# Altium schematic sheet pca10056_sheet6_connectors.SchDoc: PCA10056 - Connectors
size A3; Organization: Nordic Semiconductor; DocumentNumber: 6; SheetNumber: 6; SheetTotal: 7; CompanyName: Nordic Semiconductor
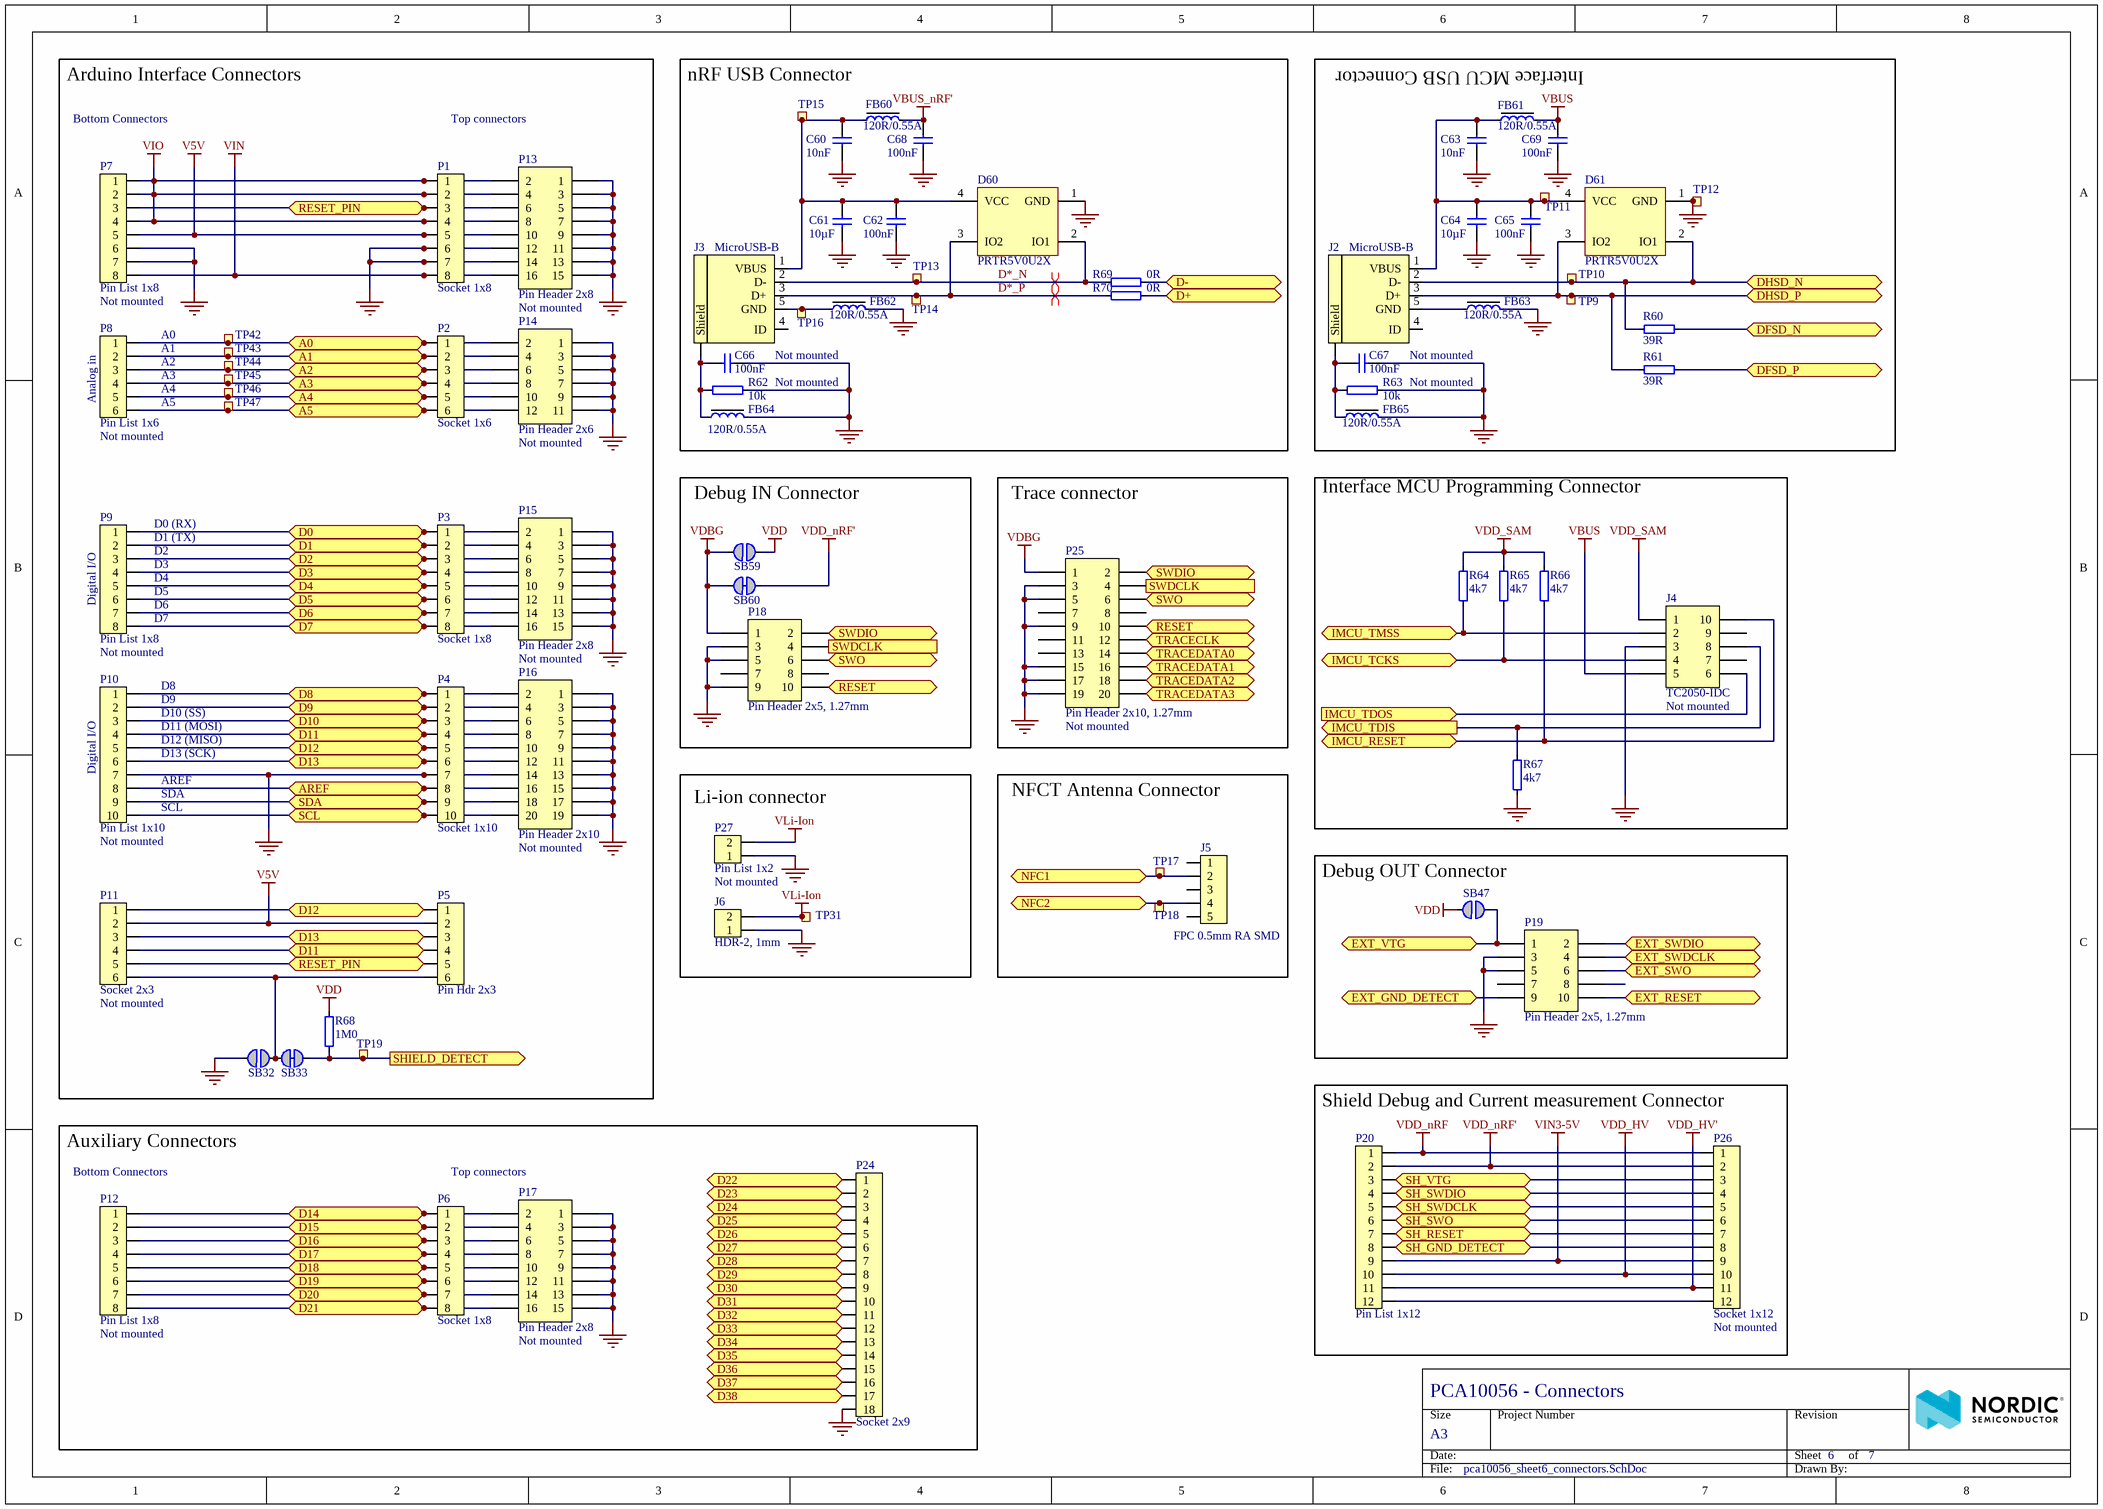
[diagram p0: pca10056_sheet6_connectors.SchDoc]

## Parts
C60  10nF  [CAPC1005X04L]
C61  10µF  [CAPC1608X06L]
C62  100nF  [CAPC1005X04L]
C63  10nF  [CAPC1005X04L]
C64  10µF  [CAPC1608X06L]
C65  100nF  [CAPC1005X04L]
C66  100nF  Assembly: Not mounted  [CAPC1005X04L]
C67  100nF  Assembly: Not mounted  [CAPC1005X04L]
C68  100nF  [CAPC1005X04L]
C69  100nF  [CAPC1005X04L]
D60  PRTR5V0U2X  [SOT190P230X110-4L]
D61  PRTR5V0U2X  [SOT190P230X110-4L]
FB60  120R/0.55A  [INDC1005X04L]
FB61  120R/0.55A  [INDC1005X04L]
FB62  120R/0.55A  [INDC1005X04L]
FB63  120R/0.55A  [INDC1005X04L]
FB64  120R/0.55A  [INDC1005X04L]
FB65  120R/0.55A  [INDC1005X04L]
J2  MicroUSB-B  [USB-Micro-B-RA-SMD-PiP]
J3  MicroUSB-B  [USB-Micro-B-RA-SMD-PiP]
J4  TC2050-IDC  Assembly: Not mounted  [TC2050-IDC-NLFP]
J5  FPC 0.5mm RA SMD  [FPC_05P-0.5mm-RA-SMD]
J6  HDR-2, 1mm  [SM02B-SRSS-TB]
P1  Socket 1x8  [SOCKET_1x8_SMD]
P2  Socket 1x6  [SOCKET_1x6_SMD]
P3  Socket 1x8  [SOCKET_1x8_SMD]
P4  Socket 1x10  [SOCKET_1x10_SMD]
P5  Pin Hdr 2x3  [HDR_2x3-SMD]
P6  Socket 1x8  [SOCKET_1x8_SMD]
P7  Pin List 1x8  Assembly: Not mounted  [LIST_1x8_SMD-NC]
P8  Pin List 1x6  Assembly: Not mounted  [LIST_1x6_SMD-NC]
P9  Pin List 1x8  Assembly: Not mounted  [LIST_1x8_SMD-NC]
P10  Pin List 1x10  Assembly: Not mounted  [LIST_1x10_SMD-NC]
P11  Socket 2x3  Assembly: Not mounted  [SOCKET_2x3_SMD-2.54mm-bottom-NC]
P12  Pin List 1x8  Assembly: Not mounted  [LIST_1x8_SMD-NC]
P13  Pin Header 2x8  Assembly: Not mounted  [HDR_2x8-NC]
P14  Pin Header 2x6  Assembly: Not mounted  [HDR_2x6-NC]
P15  Pin Header 2x8  Assembly: Not mounted  [HDR_2x8-NC]
P16  Pin Header 2x10  Assembly: Not mounted  [HDR_2x10-NC]
P17  Pin Header 2x8  Assembly: Not mounted  [HDR_2x8-NC]
P18  Pin Header 2x5, 1.27mm  [HDR_2x5-SMD-1.27mm-K]
P19  Pin Header 2x5, 1.27mm  [HDR_2x5-SMD-1.27mm-K]
P20  Pin List 1x12  [LIST_1x12_SMD]
P24  Socket 2x9  [SOCKET_2x9_SMD-2.54mm]
P25  Pin Header 2x10, 1.27mm  Assembly: Not mounted  [HDR_2x10-SMD-1.27mm-NC]
P26  Socket 1x12  Assembly: Not mounted  [LIST_1x12_SMD-NC]
P27  Pin List 1x2  Assembly: Not mounted  [LIST_1x2-NC]
R60  39R  [RESC1005X04L]
R61  39R  [RESC1005X04L]
R62  10k  Assembly: Not mounted  [RESC1005X04L]
R63  10k  Assembly: Not mounted  [RESC1005X04L]
R64  4k7  [RESC1005X04L]
R65  4k7  [RESC1005X04L]
R66  4k7  [RESC1005X04L]
R67  4k7  [RESC1005X04L]
R68  1M0  [RESC1005X04L]
R69  0R  [RESC1005X04L]
R70  0R  [RESC1005X04L]
SB32  Solderbridge  [Solderbridge]  (value not drawn)  (no BOM)
SB33  Solderbridge  [Solderbridge_Shorted]  (value not drawn)  (net tie, no BOM)
SB47  Solderbridge  [Solderbridge]  (value not drawn)  (no BOM)
SB59  Solderbridge  [Solderbridge]  (value not drawn)  (no BOM)
SB60  Solderbridge  [Solderbridge_Shorted]  (value not drawn)  (net tie, no BOM)
TP9  Ø1.0mm,SMD  [TP_SMD_Ø1.0mm]  (value not drawn)  (no BOM)
TP10  Ø1.0mm,SMD  [TP_SMD_Ø1.0mm]  (value not drawn)  (no BOM)
TP11  Ø1.0mm,SMD  [TP_SMD_Ø1.0mm]  (value not drawn)  (no BOM)
TP12  Ø1.0mm,SMD  [TP_SMD_Ø1.0mm]  (value not drawn)  (no BOM)
TP13  Ø1.5mm,SMD  [TP_SMD_Ø1.5mm]  (value not drawn)  (no BOM)
TP14  Ø1.5mm,SMD  [TP_SMD_Ø1.5mm]  (value not drawn)  (no BOM)
TP15  Ø1.5mm,SMD  [TP_SMD_Ø1.5mm]  (value not drawn)  (no BOM)
TP16  Ø1.5mm,SMD  [TP_SMD_Ø1.5mm]  (value not drawn)  (no BOM)
TP17  Ø1.0mm,SMD  [TP_SMD_Ø1.0mm]  (value not drawn)  (no BOM)
TP18  Ø1.0mm,SMD  [TP_SMD_Ø1.0mm]  (value not drawn)  (no BOM)
TP19  Ø1.0mm,SMD  [TP_SMD_Ø1.0mm]  (value not drawn)  (no BOM)
TP31  Ø1.0mm,SMD  [TP_SMD_Ø1.0mm]  (value not drawn)  (no BOM)
TP42  Ø1.0mm,SMD  [TP_SMD_Ø1.0mm]  (value not drawn)  (no BOM)
TP43  Ø1.0mm,SMD  [TP_SMD_Ø1.0mm]  (value not drawn)  (no BOM)
TP44  Ø1.0mm,SMD  [TP_SMD_Ø1.0mm]  (value not drawn)  (no BOM)
TP45  Ø1.0mm,SMD  [TP_SMD_Ø1.0mm]  (value not drawn)  (no BOM)
TP46  Ø1.0mm,SMD  [TP_SMD_Ø1.0mm]  (value not drawn)  (no BOM)
TP47  Ø1.0mm,SMD  [TP_SMD_Ø1.0mm]  (value not drawn)  (no BOM)

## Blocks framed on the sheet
Arduino Interface Connectors: P1-P5 P7-P11 P13-P16 R68 SB32 SB33 TP19 TP42-TP47
nRF USB Connector: C60-C62 C66 C68 D60 FB60 FB62 FB64 J3 R62 R69 R70 TP13-TP16
Interface MCU USB Connector: C63-C65 C67 C69 D61 FB61 FB63 FB65 J2 R60 R61 R63 TP9-TP12
Debug IN Connector: P18 SB59 SB60
Trace connector: P25
Interface MCU Programming Connector: J4 R64-R67
Li-ion connector: J6 P27 TP31
NFCT Antenna Connector: J5 TP17 TP18
Debug OUT Connector: P19 SB47
Shield Debug and Current measurement Connector: P20 P26
Auxiliary Connectors: P6 P12 P17 P24

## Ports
A0 (bidir), A1 (bidir), A2 (bidir), A3 (bidir), A4 (bidir), A5 (bidir), AREF (bidir), D0 (bidir), D1 (bidir), D2 (bidir), D3 (bidir), D4 (bidir), D5 (bidir), D6 (bidir), D7 (bidir), D8 (bidir), D9 (bidir), D10 (bidir), D11 (bidir), D12 (bidir), D13 (bidir), D14 (bidir), D15 (bidir), D16 (bidir), D17 (bidir), D18 (bidir), D19 (bidir), D20 (bidir), D21 (bidir), D22 (bidir), D23 (bidir), D24 (bidir), D25 (bidir), D26 (bidir), D27 (bidir), D28 (bidir), D29 (bidir), D30 (bidir), D31 (bidir), D32 (bidir), D33 (bidir), D34 (bidir), D35 (bidir), D36 (bidir), D37 (bidir), D38 (bidir), D+ (bidir), D- (bidir), DFSD_N (bidir), DFSD_P (bidir), DHSD_N (bidir), DHSD_P (bidir), EXT_GND_DETECT (bidir), EXT_RESET (bidir), EXT_SWDCLK (bidir), EXT_SWDIO (bidir), EXT_SWO (bidir), EXT_VTG (bidir), IMCU_RESET (bidir), IMCU_TCKS (bidir), IMCU_TDIS (out), IMCU_TDOS (in), IMCU_TMSS (bidir), NFC1 (bidir), NFC2 (bidir), RESET (bidir), RESET_PIN (bidir), SCL (bidir), SDA (bidir), SH_GND_DETECT (bidir), SH_RESET (bidir), SH_SWDCLK (bidir), SH_SWDIO (bidir), SH_SWO (bidir), SH_VTG (bidir), SHIELD_DETECT (out), SWDCLK (out), SWDIO (bidir), SWO (bidir), TRACECLK (bidir), TRACEDATA0 (bidir), TRACEDATA1 (bidir), TRACEDATA2 (bidir), TRACEDATA3 (bidir)

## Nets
GND: C60.1 C61.1 C62.1 C63.2 C64.1 C65.1 C66.1 C67.1 C68.1 C69.1 D60.1(GND) D61.1(GND) FB62.2 FB63.2 FB64.2 FB65.2 J4.3 J6.1 P1.6 P1.7 P4.7 P7.6 P7.7 P10.7 P13.1 P13.3 P13.5 P13.7 P13.9 P13.11 P13.12 P13.13 P13.14 P13.15 P14.1 P14.3 P14.5 P14.7 P14.9 P14.11 P15.1 P15.3 P15.5 P15.7 P15.9 P15.11 P15.13 P15.15 P16.1 P16.3 P16.5 P16.7 P16.9 P16.11 P16.13 P16.14 P16.15 P16.17 P16.19 P17.1 P17.3 P17.5 P17.7 P17.9 P17.11 P17.13 P17.15 P18.3 P18.5 P18.9 P19.3 P19.5 P24.18 P25.3 P25.5 P25.9 P25.15 P25.17 P25.19 P27.1 R62.1 R63.1 R67.2 SB32.1 TP12.1
V5V: P1.5 P5.2 P7.5 P11.2 P13.10
VBUS: C69.2 FB61.2 J4.5
VBUS_nRF': C68.2 FB60.2
VDBG: P18.1 P25.1 SB59.1 SB60.1
VDD: R68.2 SB47.1 SB59.2
VDD_HV: P20.10 P26.10
VDD_HV': P20.11 P26.11
VDD_nRF: P20.1 P26.1
VDD_nRF': P20.2 P26.2 SB60.2
VDD_SAM: J4.1 R64.2 R65.2 R66.2
VIN: P1.8 P7.8 P13.16
VIN3-5V: P20.9 P26.9
VIO: P1.1 P1.2 P1.4 P7.1 P7.2 P7.4 P13.2 P13.4 P13.8
VLi-Ion: J6.2 P27.2 TP31.1
A0: P2.1 P8.1 P14.2 TP42.1 ; port A0
A1: P2.2 P8.2 P14.4 TP43.1 ; port A1
A2: P2.3 P8.3 P14.6 TP44.1 ; port A2
A3: P2.4 P8.4 P14.8 TP45.1 ; port A3
A4: P2.5 P8.5 P14.10 TP46.1 ; port A4
A5: P2.6 P8.6 P14.12 TP47.1 ; port A5
AREF: P4.8 P10.8 P16.16 ; port AREF
D0: P3.1 P9.1 P15.2 ; port D0
D1: P3.2 P9.2 P15.4 ; port D1
D2: P3.3 P9.3 P15.6 ; port D2
D3: P3.4 P9.4 P15.8 ; port D3
D4: P3.5 P9.5 P15.10 ; port D4
D5: P3.6 P9.6 P15.12 ; port D5
D6: P3.7 P9.7 P15.14 ; port D6
D7: P3.8 P9.8 P15.16 ; port D7
D8: P4.1 P10.1 P16.2 ; port D8
D9: P4.2 P10.2 P16.4 ; port D9
D10: P4.3 P10.3 P16.6 ; port D10
D11: P4.4 P5.4 P10.4 P11.4 P16.8 ; port D11
D12: P4.5 P5.1 P10.5 P11.1 P16.10 ; port D12
D13: P4.6 P5.3 P10.6 P11.3 P16.12 ; port D13
D14: P6.1 P12.1 P17.2 ; port D14
D15: P6.2 P12.2 P17.4 ; port D15
D16: P6.3 P12.3 P17.6 ; port D16
D17: P6.4 P12.4 P17.8 ; port D17
D18: P6.5 P12.5 P17.10 ; port D18
D19: P6.6 P12.6 P17.12 ; port D19
D20: P6.7 P12.7 P17.14 ; port D20
D21: P6.8 P12.8 P17.16 ; port D21
D22: P24.1 ; port D22
D23: P24.2 ; port D23
D24: P24.3 ; port D24
D25: P24.4 ; port D25
D26: P24.5 ; port D26
D27: P24.6 ; port D27
D28: P24.7 ; port D28
D29: P24.8 ; port D29
D30: P24.9 ; port D30
D31: P24.10 ; port D31
D32: P24.11 ; port D32
D33: P24.12 ; port D33
D34: P24.13 ; port D34
D35: P24.14 ; port D35
D36: P24.15 ; port D36
D37: P24.16 ; port D37
D38: P24.17 ; port D38
D*_N: D60.2(IO1) J3.2(D-) R69.2 TP13.1
D*_P: D60.3(IO2) J3.3(D+) R70.2 TP14.1
D+: R70.1 ; port D+
D-: R69.1 ; port D-
DFSD_N: R60.1 ; port DFSD_N
DFSD_P: R61.1 ; port DFSD_P
DHSD_N: D61.2(IO1) J2.2(D-) R60.2 TP10.1 ; port DHSD_N
DHSD_P: D61.3(IO2) J2.3(D+) R61.2 TP9.1 ; port DHSD_P
EXT_GND_DETECT: P19.9 ; port EXT_GND_DETECT
EXT_RESET: P19.10 ; port EXT_RESET
EXT_SWDCLK: P19.4 ; port EXT_SWDCLK
EXT_SWDIO: P19.2 ; port EXT_SWDIO
EXT_SWO: P19.6 ; port EXT_SWO
EXT_VTG: P19.1 SB47.2 ; port EXT_VTG
IMCU_RESET: J4.10 R66.1 ; port IMCU_RESET
IMCU_TCKS: J4.4 R65.1 ; port IMCU_TCKS
IMCU_TDIS: J4.8 R67.1 ; port IMCU_TDIS
IMCU_TDOS: J4.6 ; port IMCU_TDOS
IMCU_TMSS: J4.2 R64.1 ; port IMCU_TMSS
NFC1: J5.2 TP17.1 ; port NFC1
NFC2: J5.4 TP18.1 ; port NFC2
RESET: P18.10 P25.10 ; port RESET
RESET_PIN: P1.3 P5.5 P7.3 P11.5 P13.6 ; port RESET_PIN
SCL: P4.10 P10.10 P16.20 ; port SCL
SDA: P4.9 P10.9 P16.18 ; port SDA
SH_GND_DETECT: P20.8 P26.8 ; port SH_GND_DETECT
SH_RESET: P20.7 P26.7 ; port SH_RESET
SH_SWDCLK: P20.5 P26.5 ; port SH_SWDCLK
SH_SWDIO: P20.4 P26.4 ; port SH_SWDIO
SH_SWO: P20.6 P26.6 ; port SH_SWO
SH_VTG: P20.3 P26.3 ; port SH_VTG
SHIELD_DETECT: R68.1 SB33.2 TP19.1 ; port SHIELD_DETECT
SWDCLK: P18.4 P25.4 ; port SWDCLK
SWDIO: P18.2 P25.2 ; port SWDIO
SWO: P18.6 P25.6 ; port SWO
TRACECLK: P25.12 ; port TRACECLK
TRACEDATA0: P25.14 ; port TRACEDATA0
TRACEDATA1: P25.16 ; port TRACEDATA1
TRACEDATA2: P25.18 ; port TRACEDATA2
TRACEDATA3: P25.20 ; port TRACEDATA3
NetC60_2: C60.2 C61.2 C62.2 D60.4(VCC) FB60.1 J3.1(VBUS) TP15.1
NetC63_1: C63.1 C64.2 C65.2 D61.4(VCC) FB61.1 J2.1(VBUS) TP11.1
NetC66_2: C66.2 FB64.1 J3.6(Shield) R62.2
NetC67_2: C67.2 FB65.1 J2.6(Shield) R63.2
NetFB62_1: FB62.1 J3.5(GND) TP16.1
NetFB63_1: FB63.1 J2.5(GND)
NetP5_6: P5.6 P11.6 SB32.2 SB33.1
NetP20_12: P20.12 P26.12

Not connected (* = marked no-connect by the designer): J2 4(ID); J3 4(ID); J4 7 9; J5 1 3 5; P18 7 8; P19 7 8; P25 7 8 11 13

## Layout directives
differential pair: D*_N, D*_P

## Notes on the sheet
- Bottom Connectors
- Top connectors
- (near P8) A0
- (near P8) A1
- (near P8) A2
- (near P8) A3
- (near P8) Analog in
- (near P8) A4
- (near P8) A5
- (near P9) D0 (RX)
- (near P9) D1 (TX)
- (near P9) D2
- (near P9) D3
- (near P9) D4
- (near P9) Digital I/O
- (near P9) D5
- (near P9) D6
- (near P9) D7
- (near P10) D8
- (near P10) D9
- (near P10) D10 (SS)
- (near P10) Digital I/O
- (near P10) AREF
- (near P10) D11 (MOSI)
- (near P10) D12 (MISO)
- (near P10) D13 (SCK)
- (near P10) SDA
- (near P10) SCL
- (near P12) Bottom Connectors

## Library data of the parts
C60 C63 = C0402-10n: Capacitor, X7R, ±10%; Part number IPS: 00000007784; Note: 16V; Artikkelnr Noca: 20039166; Artikkelnr Simpro: N.A.
C61 C64 = C0603-10µ: Capacitor, X5R, ±20%; Part number IPS: 00000007785; Note: 6.3V; Artikkelnr Noca: 20039234; Artikkelnr Simpro: N.A.
C62 C65-C69 = C0402-100n: Capacitor, X7R, ±10%; Part number IPS: 00000005296; Note: 16V; Artikkelnr Noca: 20039200; Artikkelnr Simpro: N.A.
D60 D61 = PRTR5V0U2X: Ultra low capacitance double rail-to-rail ESD protection diode; Manufacturer: NXP; 2nd source part number: 152-4157; Artikkelnr Noca: 10069015; Artikkelnr Simpro: N.A.
FB60-FB65 = FB0402-120R@100M-500mA: Ferrite Bead, 120 Ohm @ 100MHz, 500mA, 250 mOhm Max; Manufacturer: Murata; Manufacturer Part Number: BLM15AG121SN1D; 2nd source part number: 151-5760; Note: Chip EMIFIL Inductor Type Chip Ferrite Bead; Artikkelnr Noca: 33029317; Artikkelnr Simpro: N.A.
J2 J3 = USB-Micro-B-RA-SMD-PiP: MicroUSB-B-SMT; Manufacturer: Allen Creations Corp.; Manufacturer Part Number: AJU55-BS2111-L; 2nd source part number: 609-4616-1-ND; Part number IPS: 00000007790; Artikkelnr Noca: 55029020; Artikkelnr Simpro: N.A.
J4 = TC2050-IDC-NLFP: CBL PLUG-OF-NAILS 10-PIN; Manufacturer: Tag-Connect LLC; Artikkelnr Noca: N.A.
J5 = FPC_05P-0.5mm-RA-SMD: 0.5mm FPC, 5P,Right Angle SMT,Double Contact,H=1.2mm,White, Tin plated; Manufacturer: W-CON; Manufacturer Part Number: 5141-05RZDNWR01; 2nd source part number: WM9836CT-ND; Part number IPS: 00000007792; Artikkelnr Noca: 55010020; Artikkelnr Simpro: N.A.
J6 = SM02B-SRSS-TB: 1.0mm pitch connector side entry SMD; Manufacturer: JST; Manufacturer Part Number: SM02B-SRSS-TB(LF)(SN); Part number IPS: 00000007791; Note: JST, Header; Artikkelnr Noca: 55010030; Artikkelnr Simpro: N.A.
P1 P3 P6 = Socket 1x8 SMD: Socket 1x8, 2.54mm (100mil), SMD; Manufacturer: W-CON; Manufacturer Part Number: 2171-108MS0CUNR1; 2nd source part number: SSM-108-F-SV-P-TR; Artikkelnr Noca: 55030002; Artikkelnr Simpro: N.A.
P2 = Socket 1x6 SMD: Socket 1x6, 2.54mm (100mil), SMD; Manufacturer: W-CON; Manufacturer Part Number: 2171-106MS0CUNR1; 2nd source part number: SSM-106-F-SV-P-TR; Artikkelnr Noca: 55030001; Artikkelnr Simpro: N.A.
P4 = Socket 1x10 SMD: Socket 1x10, 2.54mm (100mil), SMD; Manufacturer: W-CON; Manufacturer Part Number: 2171-110MS0CUNR1; 2nd source part number: SSM-110-F-SV-P-TR; Artikkelnr Noca: 55030004; Artikkelnr Simpro: N.A.
P5 = Pin Header 2x3 SMD: Pin Header 2x3, 2.54mm (100mil) SMD; Manufacturer: W-CON; Manufacturer Part Number: 1125-1203S0M116R1; 2nd source part number: TSM-103-01-L-DV; Artikkelnr Noca: 55010007; Artikkelnr Simpro: N.A.
P7 P9 P12 = Pin List 1x8 SMD, N.C.: Pin List 1x8, 2.54mm (100mil), SMD; Manufacturer: W-CON; Manufacturer Part Number: 1125-1108S0M116R2; 2nd source part number: TSM-108-01-L-SV-P-TR; Artikkelnr Noca: 55010006; Artikkelnr Simpro: N.A.
P8 = Pin List 1x6 SMD, N.C.: Pin List 1x6, 2.54mm (100mil), SMD; Manufacturer: W-CON; Manufacturer Part Number: 1125-1106S0M116R2; 2nd source part number: TSM-106-01-L-SV-P-TR; Artikkelnr Noca: 55010026; Artikkelnr Simpro: N.A.
P10 = Pin List 1x10 SMD, N.C.: Pin List 1x10, 2.54mm (100mil), SMD; Manufacturer: W-CON; Manufacturer Part Number: 1125-1110S0M116R2; 2nd source part number: TSM-110-01-L-SV-P-TR; Artikkelnr Noca: 55010028; Artikkelnr Simpro: N.A.
P11 = Socket 2x3 SMD Bottom, N.C.: Socket 2x3, 2.54mm (100mil), SMD; Manufacturer: W-CON; Manufacturer Part Number: 2171-203MS0CUNR1; 2nd source part number: SSM-103-F-DV-P-TR; Artikkelnr Noca: 55030010; Artikkelnr Simpro: N.A.
P13 P15 P17 = Pin Header 2x8, N.C.: Pin Header 2x8, 2.54mm (100mil); Artikkelnr Noca: N.A.
P14 = Pin Header 2x6, N.C.: Pin Header 2x6, 2.54mm (100mil); Artikkelnr Noca: N.A.
P16 = Pin Header 2x10, N.C.: Pin Header 2x10, 2.54mm (100mil); Artikkelnr Noca: N.A.
P18 P19 = Pin Header 2x5 SMD, 1.27mm, KS: Pin Header 2x5, 1.27mm (50mil), SMD, Keying Shroud; Manufacturer: W-CON; Manufacturer Part Number: 3132-10MS0BK00R1; 2nd source part number: FTSH-105-01-F-DV-K; Artikkelnr Noca: 55010009; Artikkelnr Simpro: N.A.
P20 = Pin List 1x12 SMD: Pin List 1x12, 2.54mm (100mil), SMD; Artikkelnr Noca: 55019293; Artikkelnr Simpro: N.A.
P24 = Socket 2x9 SMD: Socket 2x9, 2.54mm (100mil), SMD; Manufacturer: Samtec; Manufacturer Part Number: SSM-109-F-DV; Artikkelnr Noca: 55030011; Artikkelnr Simpro: N.A.
P25 = Pin Header 2x10 SMD, 1.27mm, KS, N.C.: Pin Header 2x10, 1.27mm (50mil), SMD, Keying Shroud; Manufacturer: Samtec; Manufacturer Part Number: FTSH-110-01-F-DV-K; Artikkelnr Noca: N.A.
P26 = Socket 1x12 SMD, N.C.: Socket 1x12, 2.54mm (100mil), SMD; Manufacturer: Samtec; Manufacturer Part Number: SSM-109-L-SV; Artikkelnr Noca: N.A.
P27 = Pin List 1x2, N.C.: Pin List 1x2, 2.54mm (100mil); Artikkelnr Noca: N.A.
R60 R61 = R0402-39R: Resistor, ±1%, 0.063W; Part number IPS: 00000000821; Note: Chip Res 1%; Artikkelnr Noca: 27049039; Artikkelnr Simpro: N.A.; Value Ohm: 39
R62 R63 = R0402-10k: Resistor, ±1%, 0.063W; Part number IPS: 00000002093; Note: Chip Res 1%; Artikkelnr Noca: 27049097; Artikkelnr Simpro: N.A.; Value Ohm: 10000
R64-R67 = R0402-4k7: Resistor, ±1%, 0.063W; Part number IPS: 00000003433; Note: Chip Res 1%; Artikkelnr Noca: 27049089; Artikkelnr Simpro: N.A.; Value Ohm: 4700
R68 = R0402-1M0: Resistor, ±1%, 0.063W; Part number IPS: 00000006807; Note: Chip Res 1%; Artikkelnr Noca: 27049145; Artikkelnr Simpro: N.A.; Value Ohm: 1000000
R69 R70 = R0402-0R: Resistor, ±5%, 0.063W; Note: Chip Res 5%; Artikkelnr Noca: 27049000; Artikkelnr Simpro: N.A.; Value Ohm: 0
SB32 SB47 SB59 = Solderbridge: Artikkelnr Noca: N.A.
SB33 SB60 = Solderbridge Shorted: Shorted Solderbridge; Artikkelnr Noca: N.A.
TP9-TP12 TP17-TP19 TP31 TP42-TP47 = TP_SMD_Ø1.0MM: 1.0mm circular SMD testpad; Manufacturer: Nordic Semiconductor; Artikkelnr Noca: N.A.
TP13-TP16 = TP_SMD_Ø1.5MM: 1.0mm circular SMD testpad; Manufacturer: Nordic Semiconductor; Artikkelnr Noca: N.A.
